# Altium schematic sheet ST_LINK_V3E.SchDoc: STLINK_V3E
size A3; Date: Not used; ApprovedBy: Not used; CheckedBy: Not used; Author: Not used; CompanyName: STMicroelectronics; DrawnBy: Not used; Engineer: Not used; Organization: Not used; Address1: Not used; Address2: Not used; Address3: Not used; Address4: Not used; DocumentNumber: 7; Revision: Not used; SheetNumber: 7; SheetTotal: 8
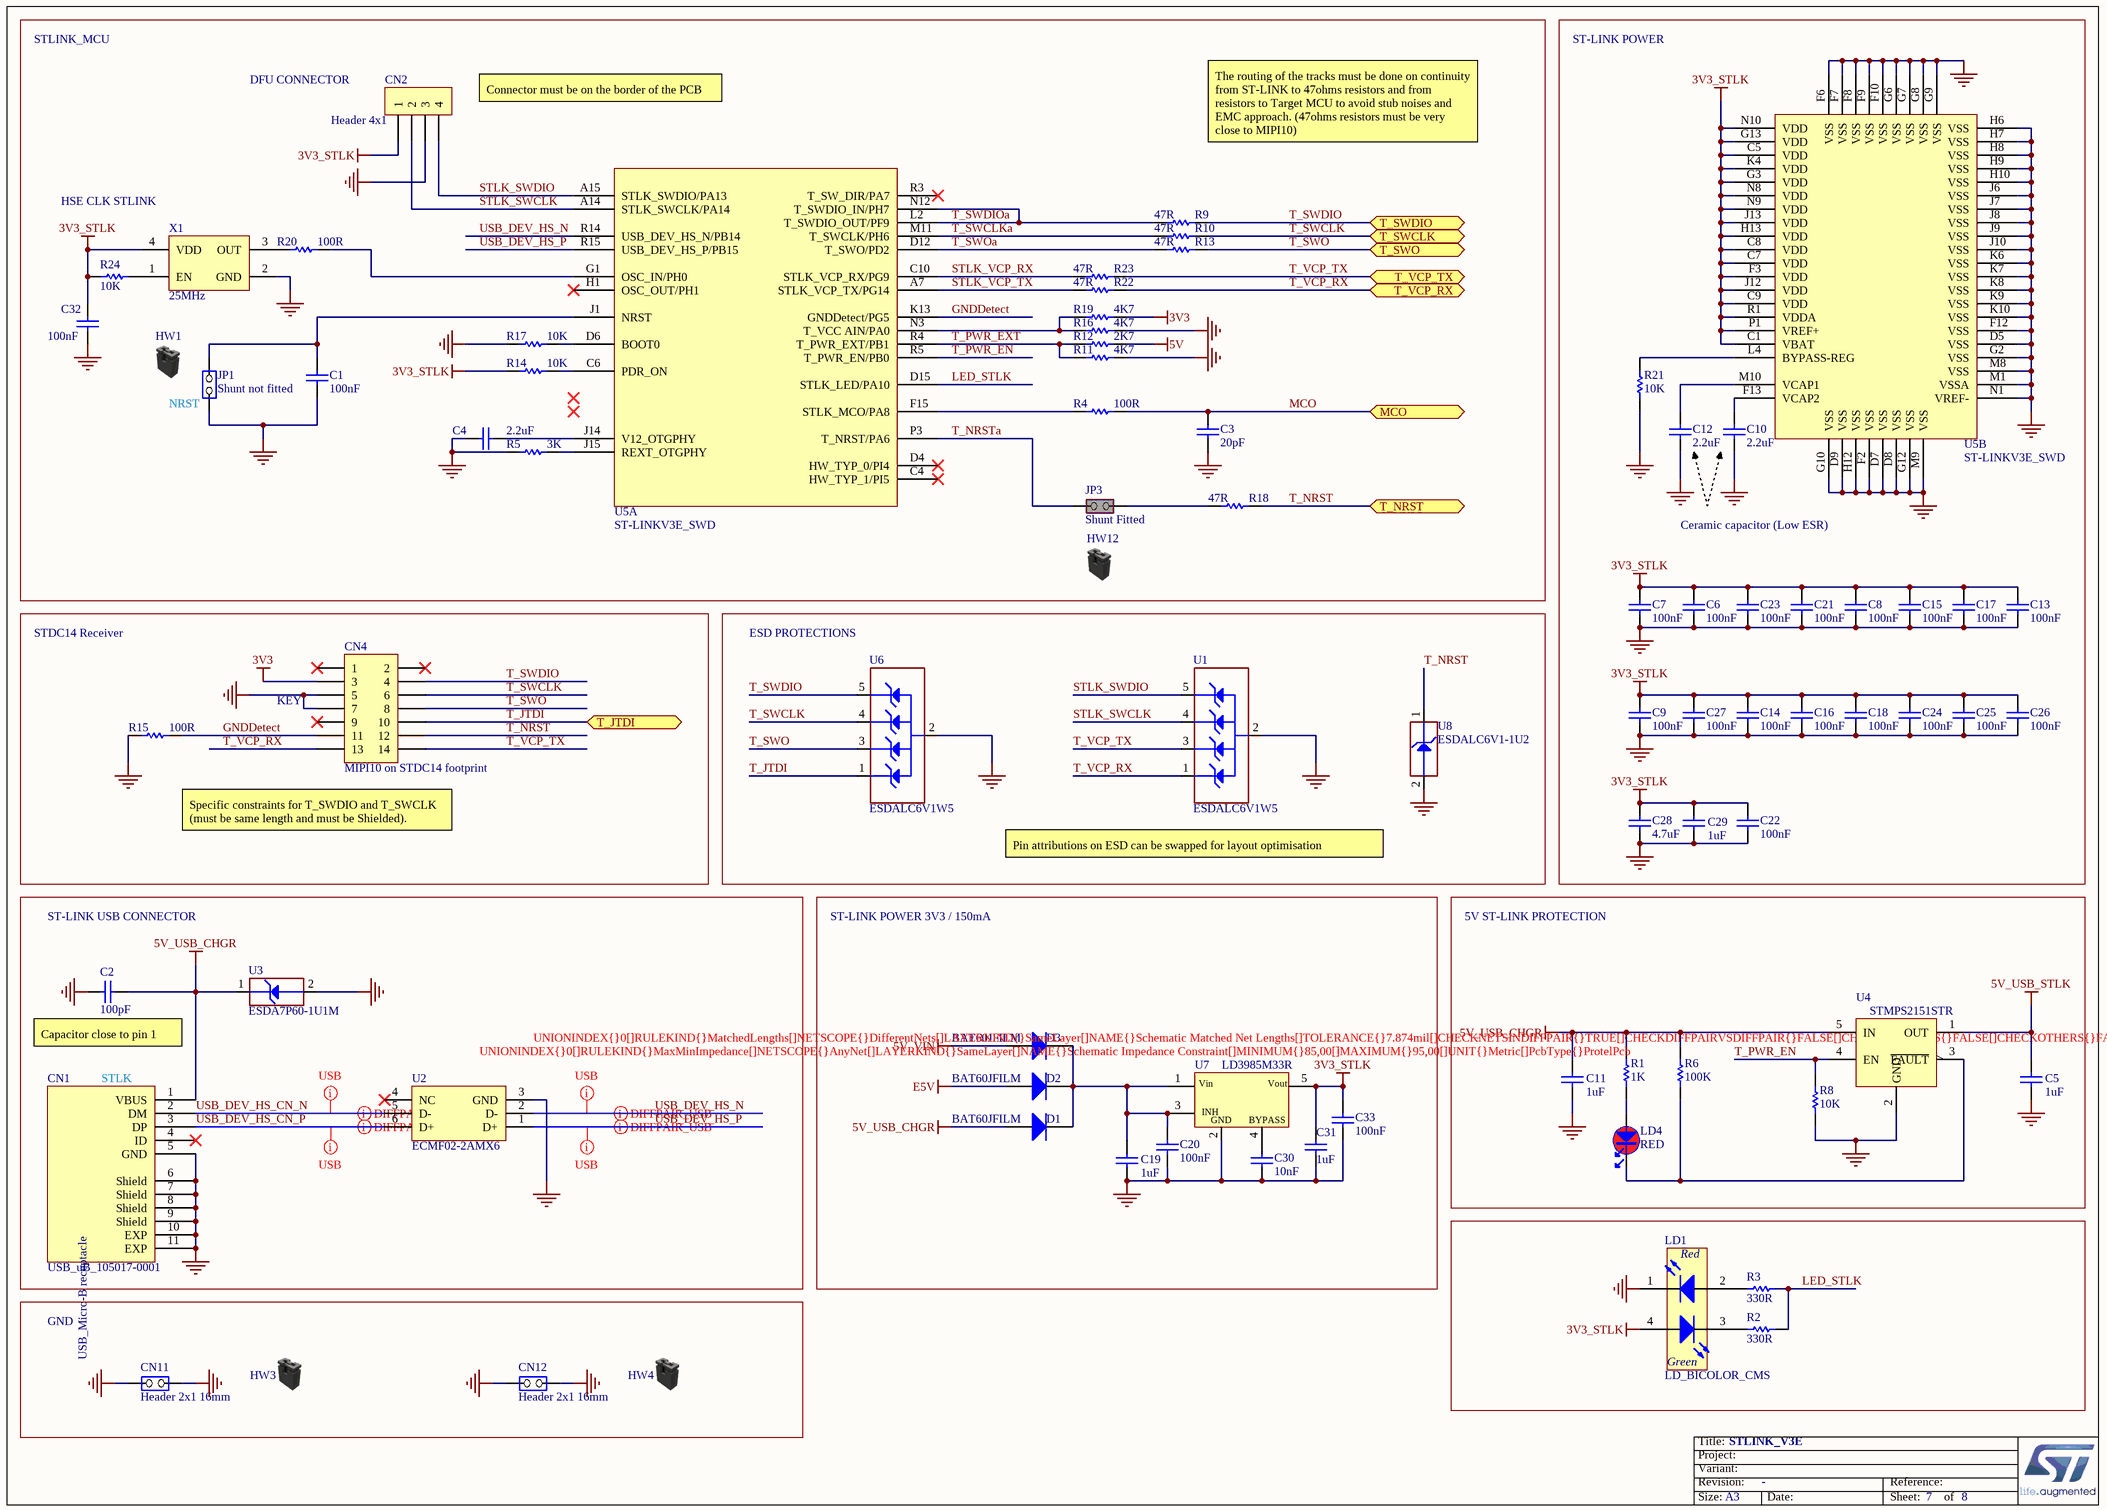
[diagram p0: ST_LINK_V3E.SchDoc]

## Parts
C1  value 100nF  [C0402]
C2  value 100pF  [C0402]
C3  value 20pF  [C0402]
C4  value 2.2uF  [C0603]
C5  value 1uF  [C0603]
C6  value 100nF  [C0402]
C7  value 100nF  [C0402]
C8  value 100nF  [C0402]
C9  value 100nF  [C0402]
C10  value 2.2uF  [C1206_H1P15]
C11  value 1uF  [C0603]
C12  value 2.2uF  [C1206_H1P15]
C13  value 100nF  [C0402]
C14  value 100nF  [C0402]
C15  value 100nF  [C0402]
C16  value 100nF  [C0402]
C17  value 100nF  [C0402]
C18  value 100nF  [C0402]
C19  value 1uF  [C0603]
C20  value 100nF  [C0402]
C21  value 100nF  [C0402]
C22  value 100nF  [C0402]
C23  value 100nF  [C0402]
C24  value 100nF  [C0402]
C25  value 100nF  [C0402]
C26  value 100nF  [C0402]
C27  value 100nF  [C0402]
C28  value 4.7uF  [C0603]
C29  value 1uF  [C0603]
C30  value 10nF  [C0402]
C31  value 1uF  [C0603]
C32  value 100nF  [C0402]
C33  value 100nF  [C0402]
CN1  value USB_uB_105017-0001  [CON_USBMICROB_MOLEX_105017-0001_H2P90]
CN2  value Header 4x1  [CON_SAMTEC_TSW-104-07-G-S]
CN4  value MIPI10 on STDC14 footprint  [CON_STDC14_Receiver_MEDIUM_WITH_MIPI10_3D]
CN11  value Header 2x1 16mm  [CON_SAMTEC_TSW-102-09-X-S]
CN12  value Header 2x1 16mm  [CON_SAMTEC_TSW-102-09-X-S]
D1  value BAT60JFILM  [DIO_SOD323]
D2  value BAT60JFILM  [DIO_SOD323]
D3  value BAT60JFILM  [DIO_SOD323]
HW1  (no value)  (mechanical)
HW3  (no value)  (mechanical)
HW4  (no value)  (mechanical)
HW12  (no value)  (mechanical)
JP1  value Shunt not fitted  [CON_SAMTEC_TSW-102-07-G-S]
JP3  Shunt Fitted  [CON_SAMTEC_TSW-102-07-G-S]
LD1  value LD_BICOLOR_CMS  [LED_BI-GR_HSMF-A201-A00J1]
LD4  value RED  [LED_0603_RED]
R1  value 1K  [R0603]
R2  value 330R  [R0603]
R3  value 330R  [R0603]
R4  value 100R  [R0402]
R5  value 3K  [R0402]
R6  value 100K  [R0603]
R8  value 10K  [R0603]
R9  value 47R  [R0402]
R10  value 47R  [R0402]
R11  value 4K7  [R0402]
R12  value 2K7  [R0402]
R13  value 47R  [R0402]
R14  value 10K  [R0402]
R15  value 100R  [R0402]
R16  value 4K7  [R0402]
R17  value 10K  [R0402]
R18  value 47R  [R0402]
R19  value 4K7  [R0402]
R20  value 100R  [R0402]
R21  value 10K  [R0402]
R22  value 47R  [R0402]
R23  value 47R  [R0402]
R24  value 10K  [R0402]
U1  value ESDALC6V1W5  [ESD_SOT323-5L]
U2  value ECMF02-2AMX6  [ESD_QFN-6L_1P7X1P5_P050]  (hidden comment: ​)
U3  value ESDA7P60-1U1M  [ESD_QFN2_1P6X1_P125]
U4  value STMPS2151STR  [MOS_SOT23-5L]
U5  value ST-LINKV3E_SWD  [ICC_UFBGA201_176+25_10X10_P065]  (parts A,B of 2)
U6  value ESDALC6V1W5  [ESD_SOT323-5L]
U7  value LD3985M33R  [REG_SOT23-5L]
U8  value ESDALC6V1-1U2  [ESD_ST0201]
X1  value 25MHz  [OSC_NDK_NZ2520SB_4P]

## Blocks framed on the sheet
ESD PROTECTIONS: U1 U6 U8
ST-LINK POWER 3V3 / 150mA: C19 C20 C30 C31 C33 D1-D3 U7
5V ST-LINK PROTECTION: C5 C11 LD4 R1 R6 R8 U4
GND: CN11 CN12 HW3 HW4

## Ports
MCO, T_JTDI, T_NRST, T_SWCLK, T_SWDIO, T_SWO, T_VCP_RX, T_VCP_TX

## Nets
3V3: CN4.3 R19.2
3V3_STLK: C6.2 C7.2 C8.2 C9.2 C13.2 C14.2 C15.2 C16.2 C17.2 C18.2 C21.2 C22.2 C23.2 C24.2 C25.2 C26.2 C27.2 C28.2 C29.2 C31.2 C32.2 C33.2 CN2.1 LD1.4(YellowGreen_anode) R14.1 R24.1 U5.C1(VBAT) U5.C5(VDD) U5.C7(VDD) U5.C8(VDD) U5.C9(VDD) U5.F3(VDD) U5.G3(VDD) U5.G13(VDD) U5.H13(VDD) U5.J12(VDD) U5.J13(VDD) U5.K4(VDD) U5.N8(VDD) U5.N9(VDD) U5.N10(VDD) U5.P1(VREF+) U5.R1(VDDA) U7.5(Vout) X1.4(VDD)
5V: R12.1
5V_USB_CHGR: C2.2 C11.2 CN1.1(VBUS) D1.1(A) R1.2 R6.2 U3.1(IO1) U4.5(IN)
5V_USB_STLK: C5.2 U4.1(OUT)
5V_VIN: D3.1(A)
E5V: D2.1(A)
GND: C1.1 C2.1 C3.1 C4.1 C5.1 C6.1 C7.1 C8.1 C9.1 C10.1 C11.1 C12.1 C13.1 C14.1 C15.1 C16.1 C17.1 C18.1 C19.1 C20.1 C21.1 C22.1 C23.1 C24.1 C25.1 C26.1 C27.1 C28.1 C29.1 C30.1 C31.1 C32.1 C33.1 CN1.5(GND) CN1.6(Shield) CN1.7(Shield) CN1.8(Shield) CN1.9(Shield) CN1.10(EXP) CN1.11(EXP) CN2.3 CN4.5 CN4.7 CN11.1(COMMON) CN11.2(NO) CN12.1(COMMON) CN12.2(NO) JP1.1(COMMON) LD1.1(RED_cathode) R5.1 R8.2 R11.1 R15.1 R16.2 R17.1 R21.1 U1.2(GND) U2.3(GND) U3.2(GND) U4.2(GND) U5.D5(VSS) U5.D7(VSS) U5.D8(VSS) U5.D9(VSS) U5.F2(VSS) U5.F6(VSS) U5.F7(VSS) U5.F8(VSS) U5.F9(VSS) U5.F10(VSS) U5.F12(VSS) U5.G2(VSS) U5.G6(VSS) U5.G7(VSS) U5.G8(VSS) U5.G9(VSS) U5.G10(VSS) U5.G12(VSS) U5.H6(VSS) U5.H7(VSS) U5.H8(VSS) U5.H9(VSS) U5.H10(VSS) U5.H12(VSS) U5.J6(VSS) U5.J7(VSS) U5.J8(VSS) U5.J9(VSS) U5.J10(VSS) U5.K6(VSS) U5.K7(VSS) U5.K8(VSS) U5.K9(VSS) U5.K10(VSS) U5.M1(VSSA) U5.M8(VSS) U5.M9(VSS) U5.N1(VREF-) U6.2(GND) U7.2(GND) U8.2(GND) X1.2(GND)
GNDDetect: CN4.11 R15.2 U5.K13(GNDDetect/PG5)
LED_STLK: R2.2 R3.2 U5.D15(STLK_LED/PA10)
MCO: C3.2 R4.2 ; port MCO
STLK_SWCLK: CN2.2 U1.4(IO3) U5.A14(STLK_SWCLK/PA14)
STLK_SWDIO: CN2.4 U1.5(IO4) U5.A15(STLK_SWDIO/PA13)
STLK_VCP_RX: R23.1 U5.C10(STLK_VCP_RX/PG9)
STLK_VCP_TX: R22.1 U5.A7(STLK_VCP_TX/PG14)
T_JTDI: CN4.10 U6.1(IO1) ; port T_JTDI
T_NRST: CN4.12 R18.2 U8.1(IO1) ; port T_NRST
T_NRSTa: JP3.1(COMMON) U5.P3(T_NRST/PA6)
T_PWR_EN: R8.1 U4.4(EN) U5.R5(T_PWR_EN/PB0)
T_PWR_EXT: R11.2 R12.2 U5.R4(T_PWR_EXT/PB1)
T_SWCLK: CN4.6 R10.2 U6.4(IO3) ; port T_SWCLK
T_SWCLKa: R10.1 U5.M11(T_SWCLK/PH6)
T_SWDIO: CN4.4 R9.2 U6.5(IO4) ; port T_SWDIO
T_SWDIOa: R9.1 U5.L2(T_SWDIO_OUT/PF9) U5.N12(T_SWDIO_IN/PH7)
T_SWO: CN4.8 R13.2 U6.3(IO2) ; port T_SWO
T_SWOa: R13.1 U5.D12(T_SWO/PD2)
T_VCP_RX: CN4.13 R22.2 U1.1(IO1) ; port T_VCP_RX
T_VCP_TX: CN4.14 R23.2 U1.3(IO2) ; port T_VCP_TX
USB_DEV_HS_CN_N: CN1.2(DM) U2.5(D-)
USB_DEV_HS_CN_P: CN1.3(DP) U2.6(D+)
USB_DEV_HS_N: U2.2(D-) U5.R14(USB_DEV_HS_N/PB14)
USB_DEV_HS_P: U2.1(D+) U5.R15(USB_DEV_HS_P/PB15)
NetC1_2: C1.2 JP1.2(NO) U5.J1(NRST)
NetC4_2: C4.2 U5.J14(V12_OTGPHY)
NetC10_2: C10.2 U5.F13(VCAP2)
NetC12_2: C12.2 U5.M10(VCAP1)
NetC19_2: C19.2 C20.2 D1.2(K) D2.2(K) D3.2(K) U7.1(Vin) U7.3(CE)
NetC30_2: C30.2 U7.4(BYPASS)
NetJP3_2: JP3.2(NO) R18.1
NetLD1_2: LD1.2(Red_anode) R3.1
NetLD1_3: LD1.3(YellowGreen_cathode) R2.1
NetLD4_1: LD4.1 R1.1
NetLD4_2: LD4.2 R6.1 U4.3(~{FAULT})
NetR4_1: R4.1 U5.F15(STLK_MCO/PA8)
NetR5_2: R5.2 U5.J15(REXT_OTGPHY)
NetR14_2: R14.2 U5.C6(PDR_ON)
NetR16_1: R16.1 R19.1 U5.N3(T_VCC_AIN/PA0)
NetR17_2: R17.2 U5.D6(BOOT0)
NetR20_1: R20.1 X1.3(OUT)
NetR20_2: R20.2 U5.G1(OSC_IN/PH0)
NetR21_2: R21.2 U5.L4(BYPASS-REG)
NetR24_2: R24.2 X1.1(EN)

Not connected (* = marked no-connect by the designer): CN1 4(ID)*; CN4 1* 2* 9*; U2 4(NC)*; U5 C4(HW_TYP_1/PI5)* D4(HW_TYP_0/PI4)* H1(OSC_OUT/PH1)* R3(T_SW_DIR/PA7)*

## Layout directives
differential pair; rule Impedance Constraint [Min = 85.00    Max = 95.00    ]: USB_DEV_HS_CN_N, USB_DEV_HS_CN_P, USB_DEV_HS_N, USB_DEV_HS_P
rule Undefined; rule Matched Net Lengths [Tolerance = 0.2mm]; rule Impedance Constraint [Min = 85.00    Max = 95.00    ]: USB_DEV_HS_CN_N, USB_DEV_HS_CN_P, USB_DEV_HS_N, USB_DEV_HS_P

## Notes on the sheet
- STLINK_MCU
- ST-LINK POWER
- DFU CONNECTOR
- (near CN2) Connector must be on the border of the PCB
- The routing of the tracks must be done on continuity from ST-LINK to 47ohms resistors and from resistors to Target MCU to avoid stub noises and EMC approach. (47ohms resistors must be very close to MIPI10)
- HSE CLK STLINK
- (near JP1) NRST
- Ceramic capacitor (Low ESR)
- STDC14 Receiver
- (near CN4) KEY
- Specific constraints for T_SWDIO and T_SWCLK (must be same length and must be Shielded).
- Pin attributions on ESD can be swapped for layout optimisation
- ST-LINK USB CONNECTOR
- (near C2) Capacitor close to pin 1
- (near CN1) STLK

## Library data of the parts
C1 C6-C9 C13-C18 C20-C27 C32 C33 = MCD-00102: Capacitor, MLCC, 100nF, 16V, X7R, 10%, 0402, T=0,5mm; Manufacturer_Part_Number: CC0402KRX7R7BB104; Manufacturer: YAGEO; Provided_By: Subcon; Initial_Board_Reference: MB1262
C2 = MCD-00205: Capacitor, MLCC, 100pF, 50V, NPO, 5%, 0402, T=0,5mm; Manufacturer_Part_Number: CC0402JRNPO9BN101; Manufacturer: YAGEO; Provided_By: Subcon
C3 = MCD-00016: Capacitor, MLCC, 20pF, 50V, NPO, 5%, 0402, T=0,5mm; Manufacturer_Part_Number: CC0402JRNPO9BN200; Manufacturer: YAGEO; Provided_By: Subcon; Initial_Board_Reference: MB1274
C4 = MCD-00012: Capacitor, MLCC, 2.2uF, 10V, X5R, 10%, 0603, T=0,8mm; Manufacturer_Part_Number: CC0603KRX5R6BB225; Manufacturer: YAGEO; Alternate_Manufacturer_Part_Number: C0603C225K8PACTU; Alternate_Manufacturer: KEMET; Provided_By: Subcon; Initial_Board_Reference: MB1274
C5 C11 C19 C29 C31 = MCD-00010: Capacitor, MLCC, 1uF, 16V, X5R, 10%, 0603, T=0,8mm; Manufacturer_Part_Number: CC0603KRX5R7BB105; Manufacturer: YAGEO; Provided_By: Subcon; Initial_Board_Reference: MB1274
C10 C12 = MCD-00008: Capacitor, MLCC, 2.2uF, 16V, X7R, 10%, 1206, T=1,15mm; Manufacturer_Part_Number: CC1206KKX7R7BB225; Manufacturer: YAGEO; Alternate_Manufacturer_Part_Number: C1206C225K4RAC; Alternate_Manufacturer: KEMET; Provided_By: Subcon; Initial_Board_Reference: MB1274
C28 = MCD-00009: Capacitor, MLCC, 4.7uF, 16V, X5R, 10%, 0603, T=0.8mm; Manufacturer_Part_Number: CC0603KRX5R7BB475; Manufacturer: YAGEO; Provided_By: subcon; Initial_Board_Reference: MB1274
C30 = MCD-00011: Capacitor, MLCC, 10nF, 16V, X7R, 10%, 0402, T=0.5mm; Manufacturer_Part_Number: CC0402KRX7R7BB103; Manufacturer: YAGEO; Provided_By: Subcon; Initial_Board_Reference: MB1274
CN1 = MCD-00028: USB-MICRO-B, 0.65mm, RA, SMT, Bottom Mount,; Manufacturer_Part_Number: 1050170001; Manufacturer: MOLEX; Part_Type: Connector; Provided_By: Subcon; Initial_Board_Reference: MB1274
CN2 = MCD-00029: Header, 4x1, 2,54mm, VR, TH, Height 5.84mm/2.54mm; Manufacturer_Part_Number: TSW-104-07-x-S; Manufacturer: SAMTEC; Part_Type: Connector; Provided_By: Subcon; Initial_Board_Reference: MB1274
CN4 = MCD-01226: Header 5x2, 1.27mm, Dual row, Straight, Surface mount, vertical male connector. 3.05mm lead. Mates with FFSD connector. Footprint compatible with FTSH-107-01-L-DV,-K,-A,-P,-ES (STDC14 MEDIUM); Manufacturer_Part_Number: FTSH-105-01-L-DV-K; Manufacturer: SAMTEC; Alternate_Manufacturer_Part_Number: P127B-2x05MGF-079-0A; Alternate_Manufacturer: JIUBABA; Provided_By: SUBCO
CN11 CN12 = MCD-00214: Header, 2x1, 2,54mm, VR, TH, Height 5.84mm/10.16mm; Part_Type: Connector; Manufacturer_Part_Number: TSW-102-09-x-S; Manufacturer: SAMTEC; Provided_By: Subcon; Initial_Board_Reference: MB1319
D1-D3 = MCD-00034: BAT60JFILM; Manufacturer: STMICROELECTRONICS; Part_Type: Diode; ECCN_US: EAR99; ECCN_EU: NEC; Provided_By: Subcon; Initial_Board_Reference: MB1274
HW1 HW3 HW4 HW12 = MCD-00043: SHUNT 2.54mm BLACK; Manufacturer_Part_Number: SNT-100-BK-G; Manufacturer: SAMTEC; Part_Type: Mechanical; Provided_By: Subcon; Initial_Board_Reference: MB1274
JP1 = MCD-00045: Header, 2x1, 2,54mm, VR, TH, Height 5.84mm/2.54mm; Part_Type: Connector; Manufacturer_Part_Number: TSW-102-07-x-S; Manufacturer: SAMTEC; Provided_By: Subcon; Initial_Board_Reference: MB1274
JP3 = MCD-00683: Header, 2x1, 2,54mm, VR, TH, Height 5.84mm/2.54mm - Shunt Fitted by default; Part_Type: Connector; Manufacturer_Part_Number: TSW-102-07-x-S; Manufacturer: SAMTEC; Provided_By: Subcon; Initial_Board_Reference: MB1331
LD1 = MCD-00051: LED Bicolor; Part_Type: Display; Manufacturer_Part_Number: HSMF-A201-A00J1; Manufacturer: AVAGO TECHNOLOGIES; Alternate_Manufacturer_Part_Number: LE-RGW35280; Alternate_Manufacturer: EVERLUCK; ECCN_US: EAR99; ECCN_EU: NEC; Provided_By: Subcon; Initial_Board_Reference: MB1274
LD4 = MCD-00049: LED, Red, 0603; Manufacturer_Part_Number: 19-213-R6C-AP1Q2B/3T; Manufacturer: EVERLIGHT; Part_Type: Display; ECCN_US: EAR99; ECCN_EU: NEC; Provided_By: Subcon; Initial_Board_Reference: MB1274
R1 = MCD-00070: Resistor,1K,0603,1%,1/10W; Manufacturer_Part_Number: RC0603FR-071KL; Manufacturer: YAGEO; Provided_By: Subcon; Initial_Board_Reference: MB1274
R2 R3 = MCD-00197: Resistor,330R,0603,1%,1/10W; Manufacturer_Part_Number: RC0603FR-07330RL; Manufacturer: YAGEO; Provided_By: Subcon
R4 R15 R20 = MCD-00119: Resistor,100R,0402,1%,1/16W; Manufacturer_Part_Number: RC0402FR-07100RL; Manufacturer: YAGEO; Provided_By: Subcon; Initial_Board_Reference: MB1262
R5 = MCD-00185: Resistor,3K,0402,1%,1/16W; Manufacturer_Part_Number: RC0402FR-073KL; Manufacturer: YAGEO; Provided_By: Subcon
R6 = MCD-00223: Resistor,100K,0603,1%,1/10W; Manufacturer_Part_Number: RC0603FR-07100KL; Manufacturer: YAGEO; Provided_By: Subcon; Initial_Board_Reference: MB1319
R8 = MCD-00220: Resistor,10K,0603,1%,1/10W; Manufacturer_Part_Number: RC0603FR-0710KL; Manufacturer: YAGEO; Provided_By: Subcon; Initial_Board_Reference: MB1319
R9 R10 R13 R18 R22 R23 = MCD-00481: Resistor,47R,0402,1%,1/16W; Manufacturer_Part_Number: RC0402FR-0747RL; Manufacturer: YAGEO; Provided_By: SUBCO; ECCN_US: EAR99; ECCN_EU: NEC
R11 R16 R19 = MCD-00065: Resistor,4K7,0402,1%,1/16W; Manufacturer_Part_Number: RC0402FR-074K7L; Manufacturer: YAGEO; Alternate_Manufacturer_Part_Number: RT0402FRE074K7L; Provided_By: Subcon; Initial_Board_Reference: MB1274
R12 = MCD-00055: Resistor,2K7,0402,1%,1/16W; Manufacturer_Part_Number: RC0402FR-072K7L; Manufacturer: YAGEO; Provided_By: Subcon; Initial_Board_Reference: MB1274
R14 R17 R21 R24 = MCD-00053: Resistor,10K,0402,1%,1/16W; Manufacturer_Part_Number: RC0402FR-0710KL; Manufacturer: YAGEO; Provided_By: subcon; Initial_Board_Reference: MB1274
U1 U6 = MCD-00136: Dual Transil array for ESD protection; Part_Type: Diode; Manufacturer: STMICROELECTRONICS; ECCN_US: EAR99; ECCN_EU: NEC; Provided_By: Subcon; Initial_Board_Reference: MB1262
U2 = MCD-00649: Common mode filter with ESD protection for USB 2.0 interface; Part_Type: Diode; Manufacturer: STMICROELECTRONICS; ECCN_US: EAR99; ECCN_EU: NEC; Provided_By: Subcon; Initial_Board_Reference: MB1248
U3 = MCD-00251: High power transient voltage suppressor, 7V breakdown; Part_Type: IC; Manufacturer: STMICROELECTRONICS; ECCN_US: EAR99; ECCN_EU: NEC; Provided_By: Subcon; Initial_Board_Reference: MB1311
U4 = MCD-00159: 500mA, Enhanced single channel power switches with active high enable pin; Part_Type: IC; Manufacturer: STMICROELECTRONICS; Alternate_Manufacturer_Part_Number: TPS2051C; Alternate_Manufacturer: TEXAS INSTRUMENTS; ECCN_US: EAR99; ECCN_EU: NEC; Provided_By: Subcon; Initial_Board_Reference: MB1264
U5 = MCD-00596: STM32F723IEK  (STM32F7) BGA176; Part_Type: IC; Manufacturer_Part_Number: STM32F723IEK6; Manufacturer: STMICROELECTRONICS; BMS_Part_Number: 9175300; Provided_By: SUBCO with ST control; ECCN_US: 3A991A2; ECCN_EU: NEC
U7 = MCD-00086: Ultra low drop-low noise BiCMOS voltage, regulators low ESR capacitors compatible; Manufacturer: STMICROELECTRONICS; Part_Type: IC; ECCN_US: EAR99; ECCN_EU: NEC; Provided_By: Subcon; Initial_Board_Reference: MB1274
U8 = MCD-00170: ESD protection 6V1; Part_Type: Diode; Manufacturer: STMICROELECTRONICS; ECCN_US: EAR99; ECCN_EU: NEC; Provided_By: Subcon; Initial_Board_Reference: MB1274
X1 = MCD-00597: Oscillator 25.00Mhz, -+50PPM, 3.3V, Temp -55 to +125°C; Manufacturer_Part_Number: NZ2520SB 25MHz END4869B; Manufacturer: NDK; Alternate_Manufacturer_Part_Number: KC2520B25.0000C10E00; Alternate_Manufacturer: AVX CORP/KYOCERA CORP; Part_Type: Crystal_Osc; Provided_By: STM; Initial_Board_Reference: MB1331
